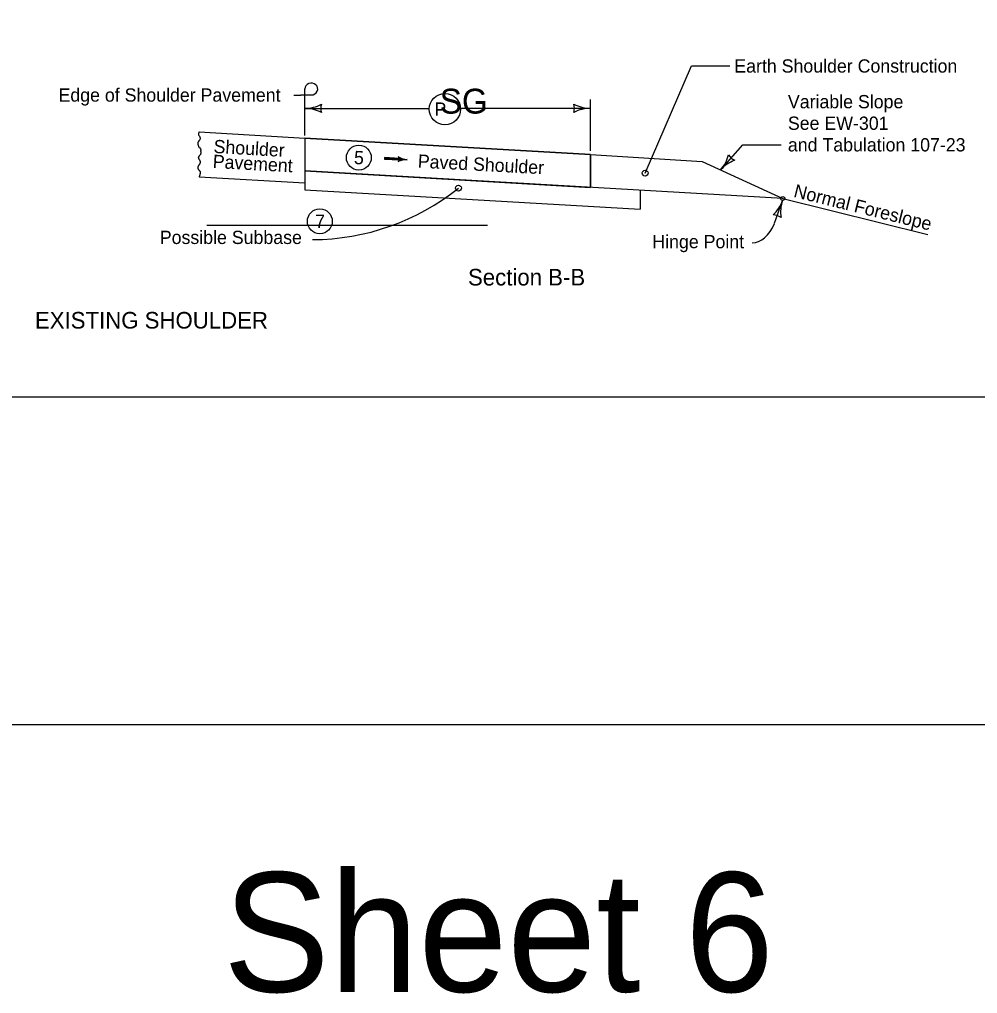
# Model space of a CAD drawing. Extents: x 9538 to 81668, y 7600 to 11751.
# Drawn here: x 29060 to 30215, y 7600 to 8774 of the extents above; entities that cross this region are included whole.
import ezdxf

# ---------------------------------------------------------------- set-up
doc = ezdxf.new("R2010")
doc.units = 0
for name, color, linetype in [('Default', 7, 'Continuous'), ('DsnShtMinorGrid13', 7, 'Continuous'), ('DsnShtMinorGrid14', 7, 'Continuous'), ('dsnStdDimension', 7, 'Continuous'), ('dsnStdNote', 7, 'Continuous'), ('dsnStdShading', 7, 'Continuous'), ('dsnStdTable', 7, 'Continuous'), ('Level 13', 7, 'Continuous')]:
    doc.layers.add(name, color=color, linetype=linetype)

msp = doc.modelspace()

# ---------------------------------------------------------------- linework, layer by layer
at = {"layer": 'Default'}
msp.add_lwpolyline([(28132.6, 9944), (31267.6, 9944), (31267.6, 7924), (28132.6, 7924)], close=True, dxfattribs=at)
at = {"layer": 'DsnShtMinorGrid13'}
for centre in [(29469.2, 8607.5), (29422.2, 8530.8)]:
    msp.add_circle(centre, 15, dxfattribs=at)
at = {"layer": 'DsnShtMinorGrid14'}
for centre in [(29814.3, 8588.9), (29589.3, 8570.8)]:
    msp.add_circle(centre, 3.54, dxfattribs=at)
at = {"layer": 'dsnStdDimension'}
for p, q in [((29748.4, 8615.7), (29748.4, 8677.4)), ((29404.1, 8666.9), (29554.1, 8666.9)), ((29591.9, 8667), (29748.4, 8667))]:
    msp.add_line(p, q, dxfattribs=at)
msp.add_circle((29573, 8666), 18.9, dxfattribs=at)
for centre, radius, start, end in [((29404.1, 8709.4), 42.5, 270, 298.0725), ((29404.1, 8624.4), 42.5, 61.9275, 90), ((29439.7, 8666.9), 16.4, 162.2666, 197.7334), ((29712.7, 8667), 16.4, 342.2666, 17.7333), ((29748.4, 8709.5), 42.5, 241.9275, 270), ((29748.4, 8624.5), 42.5, 90, 118.0725), ((29412.6, 8790.7), 282, 270.132, 308.7946)]:
    msp.add_arc(centre, radius, start, end, dxfattribs=at)
at = {"layer": 'dsnStdNote'}
for p, q in [((29814.3, 8588.9), (29870, 8718)), ((29870, 8718), (29916.4, 8718)), ((29404.1, 8670.2), (29404.1, 8691)), ((29390.7, 8683), (29399.4, 8683)), ((29411.9, 8683), (29399.4, 8683)), ((29404.1, 8634.2), (29404.1, 8670.2)), ((29905.3, 8592.6), (29931.9, 8623)), ((29931.9, 8623), (29978.3, 8623)), ((29518.3, 8605.6), (29500.1, 8606.6)), ((29518.3, 8606.6), (29518.3, 8606.6)), ((29518.2, 8604.7), (29518.2, 8604.7)), ((29970.4, 8528.4), (29979.9, 8555.9))]:
    msp.add_line(p, q, dxfattribs=at)
for points in [[(29518.4, 8606.5), (29500.2, 8607.6), (29500.1, 8605.7), (29518.2, 8604.7), (29518.3, 8606.3), (29500.4, 8607.4), (29500.4, 8605.9), (29517.9, 8604.9), (29518, 8606), (29500.6, 8607.1), (29500.6, 8606.1), (29517.6, 8605.1), (29517.7, 8605.8), (29500.8, 8606.9), (29500.8, 8606.3), (29517.4, 8605.4)], [(29518, 8607.8), (29518.7, 8606.6), (29518.6, 8605), (29517.9, 8603.6), (29520.6, 8604.4), (29523.8, 8605.1), (29524.7, 8605.2), (29522.5, 8605.8), (29519.3, 8607), (29518.3, 8607.5), (29518.4, 8604), (29523.4, 8605.2), (29518.7, 8606.8), (29518.8, 8604.4), (29522.1, 8605.3), (29519.1, 8606.2), (29518.9, 8604.8), (29521.1, 8605.3), (29519.5, 8605.8), (29519.4, 8605.2), (29520.1, 8605.3)]]:
    msp.add_lwpolyline(points, dxfattribs=at)
for centre, radius, start, end in [((29873.3, 8620.6), 42.5, 318.8454, 346.9178), ((29928.8, 8619.4), 16.4, 211.112, 246.5787), ((29937.3, 8564.6), 42.5, 110.7729, 138.8454), ((29939.7, 8569.7), 42.5, 312.9788, 341.0513), ((30020.1, 8542.1), 42.5, 161.0513, 189.1238), ((29968.3, 8522.2), 16.4, 53.3179, 88.7846)]:
    msp.add_arc(centre, radius, start, end, dxfattribs=at)
for centre, major_axis, ratio, start_param, end_param in [((29411.9, 8690.2), (-7.81, 0), 0.913811, 1.570796, 6.283185), ((29514.6, 8605.8), (3.88, 0), 0.913811, 5.202895, 7.237436), ((29529.6, 8625.2), (-22.2, 0), 0.913811, 0.954258, 1.478381), ((29526.8, 8584.8), (22.2, 0), 0.913811, 1.537172, 2.061295), ((29943.3, 8566.2), (0, 61.5), 0.559383, 3.141593, 4.048985)]:
    msp.add_ellipse(centre, major_axis=major_axis, ratio=ratio, start_param=start_param, end_param=end_param, dxfattribs=at)
at = {"layer": 'dsnStdShading'}
msp.add_line((28147.6, 8319), (31243.2, 8319), dxfattribs=at)
at = {"layer": 'dsnStdTable'}
for p, q in [((29276.6, 8638.5), (29404.1, 8631.1)), ((29404.1, 8631.1), (29404.1, 8577.1)), ((29404.1, 8631.1), (29748.4, 8611.1)), ((29748.4, 8611.1), (29404.1, 8631.1)), ((29404.1, 8631.1), (29404.1, 8591.5)), ((29747.9, 8611.3), (29747.9, 8611.3)), ((29748.3, 8611.2), (29748.3, 8571.7)), ((29748.3, 8571.7), (29748.4, 8611.1)), ((29748.4, 8611.2), (29883.1, 8602.8)), ((29883.1, 8602.8), (29980.2, 8558.3)), ((29276.6, 8584.5), (29404.1, 8577.1)), ((29980.2, 8558.3), (29404.1, 8591.5)), ((29404.1, 8591.5), (29748.3, 8571.7)), ((29404.1, 8577.1), (29404.1, 8568.7)), ((29404.1, 8568.7), (29808.3, 8545.4)), ((29808.3, 8568.2), (29808.3, 8545.4)), ((29980.2, 8558.3), (30155.2, 8515)), ((29286, 8526.2), (29624.5, 8526.2))]:
    msp.add_line(p, q, dxfattribs=at)
msp.add_circle((29469.2, 8607.5), 15, dxfattribs=at)
msp.add_ellipse((29980.2, 8558.3), major_axis=(2.58, 0), ratio=0.913811, dxfattribs=at)
for points in [[(29276.6, 8638.5), (29276.1, 8634.9), (29277.1, 8633.4), (29278, 8631.1), (29277.4, 8629.1), (29275.5, 8626.7), (29275, 8624.8), (29275.5, 8622.5), (29276.4, 8620.1), (29277.4, 8619.4), (29278.8, 8616.9), (29278.8, 8616)], [(29276.8, 8598.9), (29277, 8599.2), (29277.2, 8599.4), (29277.6, 8600), (29277.9, 8600.6), (29278, 8600.9), (29278.1, 8601.2), (29278.2, 8601.8), (29278.2, 8602.4), (29278.2, 8603), (29278.1, 8603.3), (29278.1, 8603.4), (29278.1, 8603.6), (29277.9, 8603.9), (29277.6, 8604.3), (29277.3, 8604.7), (29277, 8605.1), (29276.9, 8605.3), (29276.7, 8605.6), (29276.5, 8606.2), (29276.3, 8606.8), (29276.2, 8607.1), (29276.2, 8607.4), (29276.1, 8607.5), (29276.1, 8607.6), (29276.3, 8608.4), (29276.5, 8608.9), (29276.8, 8609.4), (29277.2, 8610.1), (29277.7, 8610.6), (29278.2, 8611.1), (29278.5, 8611.4), (29278.7, 8611.8), (29278.9, 8612.3), (29279, 8612.7), (29279.1, 8613.2), (29279.2, 8613.5), (29279.2, 8613.6), (29279.2, 8613.7), (29279.1, 8614.2), (29279, 8614.7), (29278.9, 8614.8), (29278.9, 8615), (29278.8, 8615.1), (29278.8, 8615.2), (29278.8, 8616)], [(29276.8, 8598.9), (29276.6, 8598.7), (29276.3, 8598.4), (29276.1, 8598.2), (29275.9, 8597.9), (29275.8, 8597.6), (29275.6, 8597.4), (29275.4, 8596.8), (29275.3, 8596.5), (29275.2, 8596.2), (29275.1, 8595.9), (29275.1, 8595.8), (29275.1, 8595.6), (29275.1, 8595.1), (29275.2, 8594.6), (29275.4, 8594.1), (29275.7, 8593.6), (29276.1, 8592.9), (29276.6, 8592.4), (29277.1, 8591.8), (29277.4, 8591.5), (29277.6, 8591.2), (29278, 8590.2), (29278.1, 8589.8), (29278.1, 8589.3), (29278.1, 8589), (29278, 8588.7), (29278, 8588.4), (29277.9, 8588.1), (29277.6, 8587), (29277.4, 8586.4), (29277.2, 8585.8), (29277, 8585.2), (29276.8, 8584.9), (29276.7, 8584.6), (29276.6, 8584.5)]]:
    msp.add_spline(points, degree=3, dxfattribs=at)

# ---------------------------------------------------------------- texts
at = {"layer": 'DsnShtMinorGrid13'}
msp.add_text('5', height=16, rotation=356.6997, dxfattribs=at).set_placement((29463, 8599.9))
msp.add_text('7', height=16, dxfattribs=at).set_placement((29416.5, 8522.8))
at = {"layer": 'dsnStdDimension'}
for s, height, p in [('SG', 30, (29566.7, 8660.6)), ('P', 16, (29560.3, 8658))]:
    msp.add_text(s, height=height, dxfattribs=at).set_placement(p)
at = {"layer": 'dsnStdNote'}
for s, height, p in [('Earth Shoulder Construction', 16, (29921.8, 8710)), ('Edge of Shoulder Pavement', 16, (29107.2, 8675)), ('Variable Slope', 16, (29986.4, 8667)), ('See EW-301', 16, (29986.4, 8641)), ('and Tabulation 107-23', 16, (29986.4, 8615)), ('Possible Subbase', 16, (29229.3, 8503.4)), ('Hinge Point', 16, (29823, 8498.3)), ('Section B-B', 20, (29600.8, 8453.4)), ('EXISTING SHOULDER', 20, (29078.8, 8401.5))]:
    msp.add_text(s, height=height, dxfattribs=at).set_placement(p)
for s, rotation, p in [('Shoulder', 356.7346, (29293.8, 8613.2)), ('Pavement', 356.7346, (29292.8, 8595.2)), ('Paved Shoulder ', 356.983, (29540, 8595.5)), ('Normal Foreslope', 346.0988, (29992.4, 8560.3))]:
    msp.add_text(s, height=16, rotation=rotation, dxfattribs=at).set_placement(p)
at = {"layer": 'Level 13'}
msp.add_text('Sheet 6', height=144, dxfattribs=at).set_placement((29305.6, 7602))

doc.saveas('drawing.dxf')
